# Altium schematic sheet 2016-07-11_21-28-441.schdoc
size 328 x 139 mm; SheetNumber: 1; SheetTotal: 1
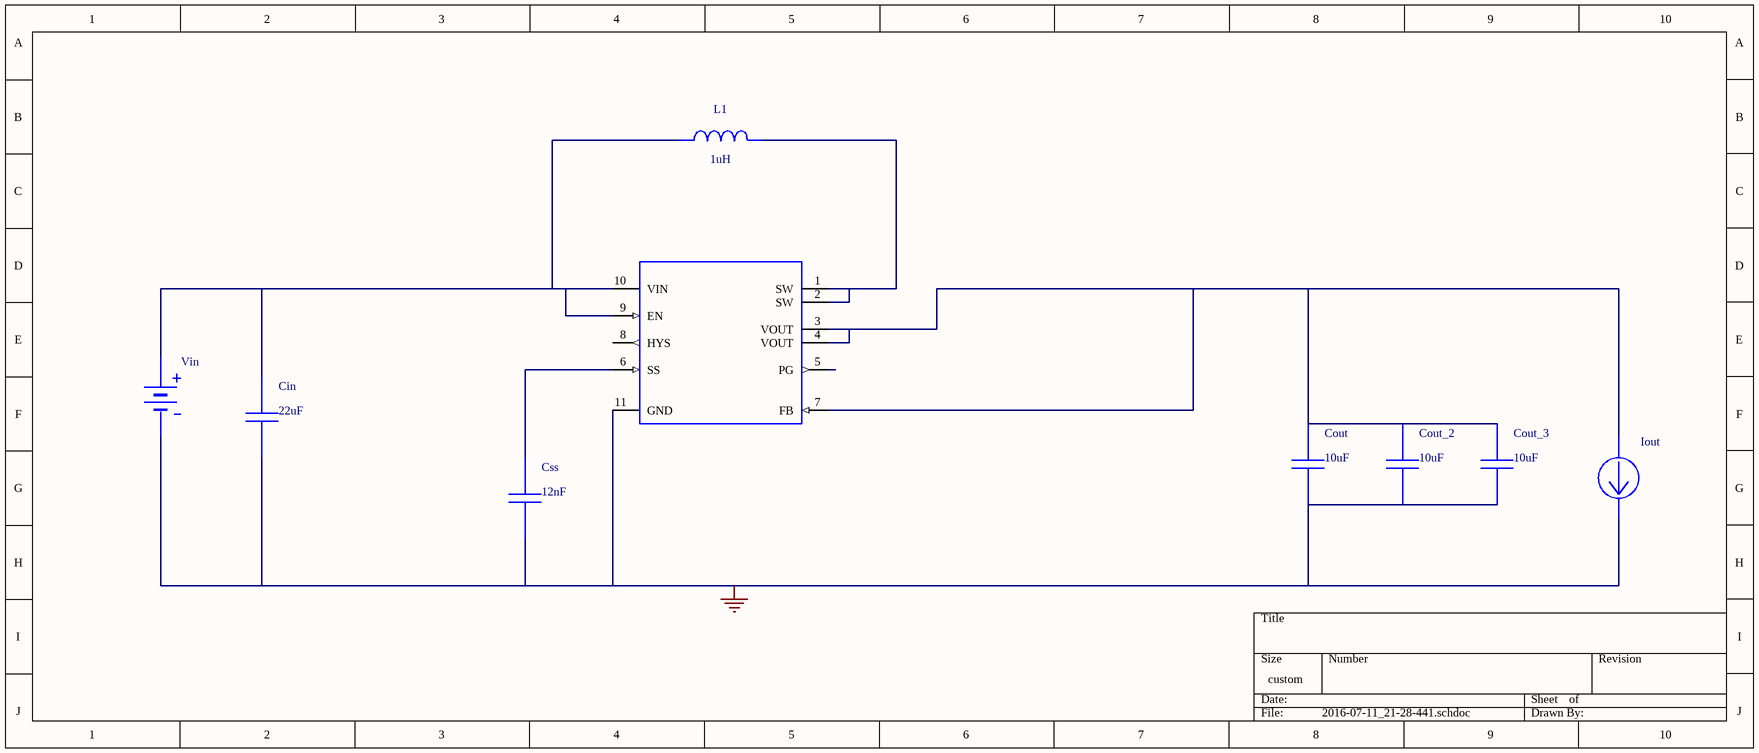
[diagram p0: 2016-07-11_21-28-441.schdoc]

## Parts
Cin  value 22uF  (hidden comment: JMK212BJ226MG-T)
Cout  value 10uF  (hidden comment: LMK212BJ106KG-T)
Cout_2  value 10uF  (hidden comment: LMK212BJ106KG-T)
Cout_3  value 10uF  (hidden comment: LMK212BJ106KG-T)
Css  value 12nF  (hidden comment: GRM033C80J123KE01D)
Iout  WB_CURRENT_LOAD  (value not drawn)
L1  value 1uH  (hidden comment: SRU1028-1R0Y)
U1  TPS61232DRCR  (value not drawn)
Vin  WB_BATTERY  (value not drawn)

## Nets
0: Cin.2 Cout.2 Cout_2.2 Cout_3.2 Css.2 Iout.2(-) U1.11(GND) Vin.2(-)
NetCin_1: Cin.1 L1.1 U1.9(EN) U1.10(VIN) Vin.1(+)
NetCout_1: Cout.1 Cout_2.1 Cout_3.1 Iout.1(+) U1.3(VOUT) U1.4(VOUT) U1.7(FB)
NetCss_1: Css.1 U1.6(SS)
NetL1_2: L1.2 U1.1(SW) U1.2(SW)

Not connected (* = marked no-connect by the designer): U1 5(PG) 8(HYS)

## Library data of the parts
Cin = JMK212BJ226MG-T: Manufacturer Name: Taiyo Yuden
Cout Cout_2 Cout_3 = LMK212BJ106KG-T: Manufacturer Name: Taiyo Yuden
Css = GRM033C80J123KE01D: GRM033C80J123KE0; Manufacturer Name: MuRata
L1 = SRU1028-1R0Y: Manufacturer Name: Bourns
U1 = TPS61232DRCR: Manufacturer Name: Texas Instruments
